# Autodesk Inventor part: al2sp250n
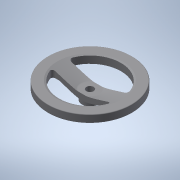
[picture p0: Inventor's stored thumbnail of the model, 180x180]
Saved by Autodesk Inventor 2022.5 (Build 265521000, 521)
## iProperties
Created: 2016-12
Part Number: al2sp250n
Material: 一般
Document SubType Name: Modeling
Designer: imaocorp
Density: 1 g/cm^3
Appearance: 既定
Author: imaocorp
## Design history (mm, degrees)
node "al2sp250n.x_t1"
node "al2sp250n"
node "Base1"
